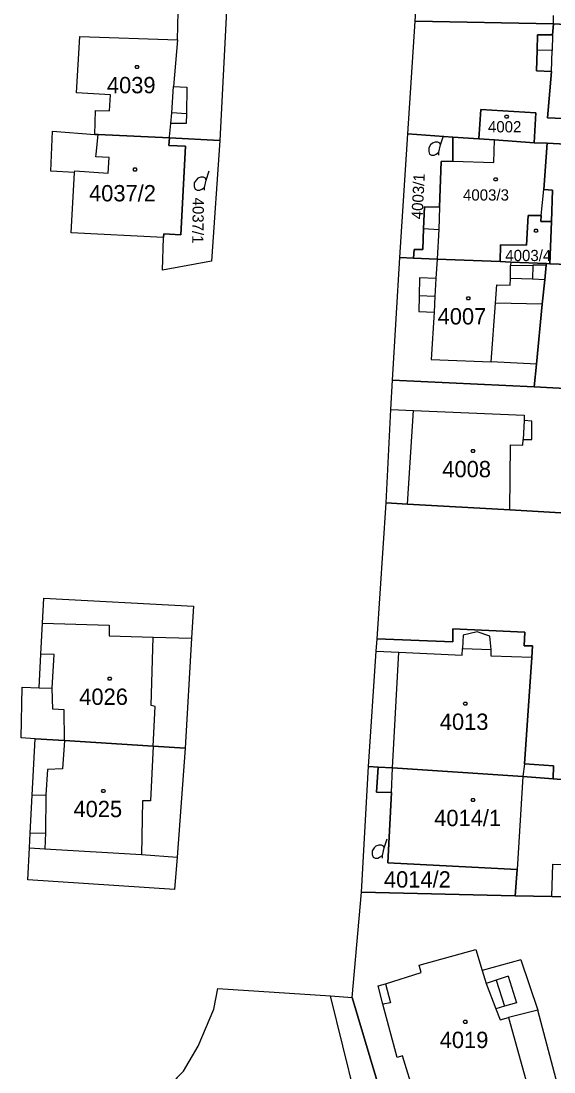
# Model space of a CAD drawing. Extents: x -263587 to -261993, y -1238795 to -1236748.
# Drawn here: x -263052.9 to -263000.7, y -1238246.6 to -1238143.7 of the extents above; entities that cross this region are included whole.
import ezdxf

# ---------------------------------------------------------------- set-up
doc = ezdxf.new("R2010")
doc.units = 0
doc.layers.add('Vrstva 1', color=7, linetype='Continuous')
doc.layers.add('Vrstva 3', color=7, linetype='Continuous')

msp = doc.modelspace()

# ---------------------------------------------------------------- linework, layer by layer
at = {"layer": 'Vrstva 1'}
for p, q in [((-263014.29, -1238143.7), (-263013.36, -1238129.11)), ((-263032.54, -1238138.12), (-263033.41, -1238155.37)), ((-263037.58, -1238145.5), (-263037.41, -1238139.05)), ((-263015.02, -1238154.73), (-263014.29, -1238143.7)), ((-263000.75, -1238143.96), (-263014.29, -1238143.7)), ((-263014.29, -1238143.7), (-263000.75, -1238143.96)), ((-263000.75, -1238143.96), (-263000.77, -1238143.14)), ((-263000.86, -1238145.03), (-263000.75, -1238143.96)), ((-263000.75, -1238143.96), (-263000.86, -1238145.03)), ((-262993.44, -1238144.36), (-263000.75, -1238143.96)), ((-263000.75, -1238143.96), (-262993.44, -1238144.36)), ((-263047.46, -1238150.72), (-263047.14, -1238145.2)), ((-263047.14, -1238145.2), (-263037.58, -1238145.5)), ((-263037.58, -1238145.5), (-263037.96, -1238150.08)), ((-263002.37, -1238146.51), (-263002.34, -1238145.02)), ((-263002.34, -1238145.02), (-263002.37, -1238146.51)), ((-263002.34, -1238145.02), (-263000.86, -1238145.03)), ((-263000.86, -1238145.03), (-263002.34, -1238145.02)), ((-263000.86, -1238145.03), (-263000.91, -1238146.56)), ((-263002.42, -1238148.56), (-263002.37, -1238146.51)), ((-263002.37, -1238146.51), (-263002.42, -1238148.56)), ((-263000.91, -1238146.56), (-263002.37, -1238146.51)), ((-263000.96, -1238148.62), (-263000.91, -1238146.56)), ((-263000.96, -1238148.62), (-263002.42, -1238148.56)), ((-263002.42, -1238148.56), (-263000.96, -1238148.62)), ((-263001.34, -1238153.14), (-263000.96, -1238148.62)), ((-263000.96, -1238148.62), (-263001.34, -1238153.14)), ((-263044.14, -1238150.9), (-263047.46, -1238150.72)), ((-263044.23, -1238152.48), (-263044.14, -1238150.9)), ((-263038.13, -1238152.65), (-263037.96, -1238150.08)), ((-263037.96, -1238150.08), (-263036.65, -1238150.15)), ((-263036.65, -1238150.15), (-263036.7, -1238152.76)), ((-263045.66, -1238154.78), (-263045.6, -1238152.45)), ((-263045.6, -1238152.45), (-263044.23, -1238152.48)), ((-263038.21, -1238153.71), (-263038.13, -1238152.65)), ((-263036.7, -1238152.76), (-263038.13, -1238152.65)), ((-263036.7, -1238152.76), (-263036.72, -1238153.72)), ((-263007.87, -1238152.35), (-263008.06, -1238155.21)), ((-263008.06, -1238155.21), (-263007.87, -1238152.35)), ((-263002.51, -1238152.66), (-263007.87, -1238152.35)), ((-263007.87, -1238152.35), (-263002.51, -1238152.66)), ((-263002.65, -1238155.59), (-263002.51, -1238152.66)), ((-263002.51, -1238152.66), (-263002.65, -1238155.59)), ((-263038.35, -1238155.02), (-263038.21, -1238153.71)), ((-263036.72, -1238153.72), (-263038.21, -1238153.71)), ((-262995.53, -1238153.46), (-263001.34, -1238153.14)), ((-263001.34, -1238153.14), (-262995.53, -1238153.46)), ((-263049.98, -1238158.38), (-263049.8, -1238154.46)), ((-263049.8, -1238154.46), (-263045.66, -1238154.78)), ((-263045.33, -1238154.8), (-263045.66, -1238154.78)), ((-263045.66, -1238154.78), (-263045.33, -1238154.8)), ((-263045.54, -1238156.73), (-263045.33, -1238154.8)), ((-263038.35, -1238155.13), (-263045.33, -1238154.8)), ((-263045.33, -1238154.8), (-263038.35, -1238155.13)), ((-263038.35, -1238155.13), (-263038.41, -1238155.88)), ((-263038.41, -1238155.88), (-263038.35, -1238155.13)), ((-263038.35, -1238155.13), (-263038.35, -1238155.02)), ((-263033.41, -1238155.37), (-263038.35, -1238155.13)), ((-263038.35, -1238155.13), (-263033.41, -1238155.37)), ((-263015.79, -1238166.84), (-263015.02, -1238154.73)), ((-263015.02, -1238154.73), (-263010.63, -1238155.04)), ((-263010.63, -1238155.04), (-263015.02, -1238154.73)), ((-263011.81, -1238155.81), (-263011.54, -1238154.91)), ((-263010.63, -1238155.04), (-263010.61, -1238157.41)), ((-263008.06, -1238155.21), (-263010.63, -1238155.04)), ((-263010.61, -1238157.41), (-263010.63, -1238155.04)), ((-263010.63, -1238155.04), (-263008.06, -1238155.21)), ((-263038.41, -1238155.88), (-263036.77, -1238155.94)), ((-263036.77, -1238155.94), (-263038.41, -1238155.88)), ((-263036.77, -1238155.94), (-263037.25, -1238164.63)), ((-263037.25, -1238164.63), (-263036.77, -1238155.94)), ((-263033.41, -1238155.37), (-263034.23, -1238167.2)), ((-263006.53, -1238155.32), (-263008.06, -1238155.21)), ((-263008.06, -1238155.21), (-263006.53, -1238155.32)), ((-263006.6, -1238157.54), (-263006.53, -1238155.32)), ((-263002.65, -1238155.59), (-263006.53, -1238155.32)), ((-263006.53, -1238155.32), (-263002.65, -1238155.59)), ((-263001.4, -1238155.65), (-263002.65, -1238155.59)), ((-263002.65, -1238155.59), (-263001.4, -1238155.65)), ((-263001.7, -1238160.19), (-263001.4, -1238155.65)), ((-263001.4, -1238155.65), (-263001.7, -1238160.19)), ((-262996.31, -1238155.93), (-263001.4, -1238155.65)), ((-263001.4, -1238155.65), (-262996.31, -1238155.93)), ((-263045.57, -1238156.98), (-263045.54, -1238156.73)), ((-263044.25, -1238157.05), (-263045.57, -1238156.98)), ((-263044.35, -1238158.59), (-263044.25, -1238157.05)), ((-263011.75, -1238157.42), (-263011.92, -1238161.9)), ((-263011.92, -1238161.9), (-263011.75, -1238157.42)), ((-263010.61, -1238157.41), (-263011.75, -1238157.42)), ((-263011.75, -1238157.42), (-263010.61, -1238157.41)), ((-263010.61, -1238157.41), (-263006.6, -1238157.54)), ((-263047.64, -1238158.52), (-263049.98, -1238158.38)), ((-263047.99, -1238164.43), (-263047.64, -1238158.52)), ((-263047.64, -1238158.52), (-263047.63, -1238158.36)), ((-263047.63, -1238158.36), (-263044.35, -1238158.59)), ((-263034.75, -1238159.25), (-263034.48, -1238158.35)), ((-263001.97, -1238162.72), (-263001.7, -1238160.19)), ((-263000.85, -1238160.25), (-263001.7, -1238160.19)), ((-263001.7, -1238160.19), (-263000.85, -1238160.25)), ((-263000.97, -1238163.32), (-263000.85, -1238160.25)), ((-263000.85, -1238160.25), (-263000.97, -1238163.32)), ((-263013.39, -1238161.87), (-263013.48, -1238164.01)), ((-263013.48, -1238164.01), (-263013.39, -1238161.87)), ((-263011.92, -1238161.9), (-263013.39, -1238161.87)), ((-263013.39, -1238161.87), (-263011.92, -1238161.9)), ((-263011.92, -1238161.9), (-263011.99, -1238164.11)), ((-263003.25, -1238162.72), (-263003.41, -1238165.63)), ((-263003.41, -1238165.63), (-263003.25, -1238162.72)), ((-263001.97, -1238162.72), (-263003.25, -1238162.72)), ((-263003.25, -1238162.72), (-263001.97, -1238162.72)), ((-263001.99, -1238163.32), (-263001.97, -1238162.72)), ((-263001.97, -1238162.72), (-263001.99, -1238163.32)), ((-263000.97, -1238163.32), (-263001.99, -1238163.32)), ((-263001.99, -1238163.32), (-263000.97, -1238163.32)), ((-263001.13, -1238167.45), (-263000.97, -1238163.32)), ((-263000.97, -1238163.32), (-263001.13, -1238167.45)), ((-263013.48, -1238164.01), (-263013.54, -1238166.05)), ((-263013.54, -1238166.05), (-263013.48, -1238164.01)), ((-263013.48, -1238164.01), (-263011.99, -1238164.11)), ((-263011.99, -1238164.11), (-263012.15, -1238166.97)), ((-263038.94, -1238164.88), (-263047.99, -1238164.43)), ((-263039.02, -1238168.08), (-263038.94, -1238164.88)), ((-263038.92, -1238164.53), (-263038.94, -1238164.88)), ((-263038.94, -1238164.88), (-263038.92, -1238164.53)), ((-263037.25, -1238164.63), (-263038.92, -1238164.53)), ((-263038.92, -1238164.53), (-263037.25, -1238164.63)), ((-263014.41, -1238166.05), (-263014.47, -1238166.9)), ((-263014.47, -1238166.9), (-263014.41, -1238166.05)), ((-263013.54, -1238166.05), (-263014.41, -1238166.05)), ((-263014.41, -1238166.05), (-263013.54, -1238166.05)), ((-263005.94, -1238165.59), (-263006, -1238167.24)), ((-263006, -1238167.24), (-263005.94, -1238165.59)), ((-263003.41, -1238165.63), (-263005.94, -1238165.59)), ((-263005.94, -1238165.59), (-263003.41, -1238165.63)), ((-263034.23, -1238167.2), (-263039.02, -1238168.08)), ((-263016.52, -1238178.87), (-263015.79, -1238166.84)), ((-263015.79, -1238166.84), (-263014.47, -1238166.9)), ((-263014.47, -1238166.9), (-263015.79, -1238166.84)), ((-263014.47, -1238166.9), (-263012.15, -1238166.99)), ((-263012.15, -1238166.99), (-263014.47, -1238166.9)), ((-263012.15, -1238166.99), (-263012.29, -1238168.89)), ((-263012.15, -1238166.97), (-263012.15, -1238166.99)), ((-263012.15, -1238166.99), (-263006, -1238167.24)), ((-263006, -1238167.24), (-263012.15, -1238166.99)), ((-263006, -1238167.24), (-263004.94, -1238167.29)), ((-263004.94, -1238167.29), (-263006, -1238167.24)), ((-263004.94, -1238167.29), (-263004.96, -1238167.61)), ((-263004.94, -1238167.29), (-263001.46, -1238167.43)), ((-263001.46, -1238167.43), (-263004.94, -1238167.29)), ((-263001.46, -1238167.43), (-263001.48, -1238167.59)), ((-263001.48, -1238167.59), (-263001.46, -1238167.43)), ((-263001.46, -1238167.43), (-263001.13, -1238167.45)), ((-263001.13, -1238167.45), (-263001.46, -1238167.43)), ((-262997.1, -1238167.63), (-263001.13, -1238167.45)), ((-263001.13, -1238167.45), (-262997.1, -1238167.63)), ((-263004.97, -1238168.91), (-263004.96, -1238167.61)), ((-263004.96, -1238167.61), (-263002.8, -1238167.6)), ((-263002.8, -1238167.6), (-263002.83, -1238168.96)), ((-263001.48, -1238167.59), (-263002.8, -1238167.6)), ((-263001.48, -1238167.59), (-263001.62, -1238169.02)), ((-263001.62, -1238169.02), (-263001.48, -1238167.59)), ((-263013.87, -1238168.84), (-263013.92, -1238170.6)), ((-263012.29, -1238168.89), (-263013.87, -1238168.84)), ((-263012.29, -1238168.89), (-263012.39, -1238170.66)), ((-263006.43, -1238171.3), (-263006.31, -1238169.53)), ((-263006.31, -1238169.53), (-263005, -1238169.54)), ((-263005, -1238169.54), (-263004.97, -1238168.91)), ((-263002.83, -1238168.96), (-263004.97, -1238168.91)), ((-263001.62, -1238169.02), (-263002.83, -1238168.96)), ((-263001.62, -1238169.02), (-263001.86, -1238171.42)), ((-263001.86, -1238171.42), (-263001.62, -1238169.02)), ((-263013.92, -1238170.6), (-263013.96, -1238172.12)), ((-263012.39, -1238170.66), (-263013.92, -1238170.6)), ((-263012.39, -1238170.66), (-263012.45, -1238172.19)), ((-263006.86, -1238177.07), (-263006.43, -1238171.3)), ((-263001.86, -1238171.42), (-263006.43, -1238171.3)), ((-263001.86, -1238171.42), (-263002.44, -1238177.29)), ((-263002.44, -1238177.29), (-263001.86, -1238171.42)), ((-263013.96, -1238172.12), (-263012.45, -1238172.19)), ((-263012.45, -1238172.19), (-263012.75, -1238176.84)), ((-263012.75, -1238176.84), (-263006.86, -1238177.07)), ((-263002.44, -1238177.29), (-263006.86, -1238177.07)), ((-263002.44, -1238177.29), (-263002.66, -1238179.51)), ((-263002.66, -1238179.51), (-263002.44, -1238177.29)), ((-263016.67, -1238181.72), (-263016.52, -1238178.87)), ((-263016.52, -1238178.87), (-263002.66, -1238179.51)), ((-263002.66, -1238179.51), (-263016.52, -1238178.87)), ((-263002.66, -1238179.51), (-262987.5, -1238180.36)), ((-262987.5, -1238180.36), (-263002.66, -1238179.51)), ((-263017.14, -1238190.88), (-263016.67, -1238181.72)), ((-263016.67, -1238181.72), (-263014.46, -1238181.83)), ((-263015.07, -1238190.99), (-263014.46, -1238181.83)), ((-263014.46, -1238181.83), (-263003.62, -1238182.27)), ((-263003.65, -1238182.82), (-263003.73, -1238184.68)), ((-263003.62, -1238182.27), (-263003.65, -1238182.82)), ((-263002.89, -1238182.87), (-263003.65, -1238182.82)), ((-263002.89, -1238184.68), (-263002.89, -1238182.87)), ((-263003.76, -1238185.21), (-263003.73, -1238184.68)), ((-263003.73, -1238184.68), (-263002.89, -1238184.68)), ((-263005.05, -1238191.56), (-263004.96, -1238185.19)), ((-263004.96, -1238185.19), (-263003.76, -1238185.21)), ((-263018.03, -1238204.21), (-263017.14, -1238190.88)), ((-263015.07, -1238190.99), (-263017.14, -1238190.88)), ((-263017.14, -1238190.88), (-263015.07, -1238190.99)), ((-263005.05, -1238191.56), (-263015.07, -1238190.99)), ((-263015.07, -1238190.99), (-263005.05, -1238191.56)), ((-262998.22, -1238191.96), (-263005.05, -1238191.56)), ((-263005.05, -1238191.56), (-262998.22, -1238191.96)), ((-263050.78, -1238202.68), (-263050.65, -1238200.22)), ((-263050.65, -1238200.22), (-263036.01, -1238201.01)), ((-263036.01, -1238201.01), (-263036.19, -1238204.09)), ((-263050.94, -1238205.69), (-263050.78, -1238202.68)), ((-263050.78, -1238202.68), (-263044.25, -1238202.86)), ((-263044.25, -1238202.86), (-263044.24, -1238203.89)), ((-263003.57, -1238203.53), (-263010.62, -1238203.23)), ((-263010.62, -1238203.23), (-263010.62, -1238204.48)), ((-263010.62, -1238204.48), (-263010.62, -1238203.23)), ((-263010.62, -1238203.23), (-263003.57, -1238203.53)), ((-263008.23, -1238203.5), (-263009.62, -1238203.84)), ((-263007.01, -1238203.94), (-263008.23, -1238203.5)), ((-263003.62, -1238204.87), (-263003.57, -1238203.53)), ((-263003.57, -1238203.53), (-263003.62, -1238204.87)), ((-263044.24, -1238203.89), (-263039.94, -1238204.05)), ((-263040.13, -1238210.73), (-263039.94, -1238204.05)), ((-263039.94, -1238204.05), (-263036.19, -1238204.12)), ((-263036.19, -1238204.12), (-263036.8, -1238214.92)), ((-263036.19, -1238204.09), (-263036.19, -1238204.12)), ((-263018.11, -1238205.42), (-263018.03, -1238204.21)), ((-263010.62, -1238204.48), (-263018.03, -1238204.21)), ((-263018.03, -1238204.21), (-263010.62, -1238204.48)), ((-263009.62, -1238203.84), (-263009.68, -1238205.15)), ((-263006.88, -1238205.25), (-263007.01, -1238203.94)), ((-263018.86, -1238216.7), (-263018.11, -1238205.42)), ((-263018.11, -1238205.42), (-263015.89, -1238205.49)), ((-263016.51, -1238216.85), (-263015.89, -1238205.49)), ((-263015.89, -1238205.49), (-263009.7, -1238205.8)), ((-263009.7, -1238205.8), (-263009.68, -1238205.15)), ((-263009.68, -1238205.15), (-263006.88, -1238205.25)), ((-263006.86, -1238205.91), (-263006.88, -1238205.25)), ((-263002.81, -1238204.89), (-263003.62, -1238204.87)), ((-263003.62, -1238204.87), (-263002.81, -1238204.89)), ((-263002.89, -1238206.03), (-263002.81, -1238204.89)), ((-263002.81, -1238204.89), (-263002.89, -1238206.03)), ((-263051.11, -1238209), (-263050.94, -1238205.69)), ((-263049.64, -1238205.72), (-263050.94, -1238205.69)), ((-263049.82, -1238209.02), (-263049.64, -1238205.72)), ((-263002.89, -1238206.03), (-263006.86, -1238205.91)), ((-263003.59, -1238216.46), (-263002.89, -1238206.03)), ((-263002.89, -1238206.03), (-263003.59, -1238216.46)), ((-263052.88, -1238213.91), (-263052.76, -1238208.92)), ((-263052.76, -1238208.92), (-263051.11, -1238209)), ((-263051.11, -1238209), (-263049.82, -1238209.02)), ((-263049.76, -1238211.09), (-263049.82, -1238209.02)), ((-263039.74, -1238210.82), (-263040.13, -1238210.73)), ((-263048.67, -1238211.14), (-263049.76, -1238211.09)), ((-263048.64, -1238214.17), (-263048.67, -1238211.14)), ((-263039.96, -1238214.72), (-263039.74, -1238210.82)), ((-263051.49, -1238213.99), (-263052.88, -1238213.91)), ((-263051.79, -1238219.53), (-263051.49, -1238213.99)), ((-263051.49, -1238213.99), (-263048.64, -1238214.17)), ((-263048.64, -1238214.17), (-263051.49, -1238213.99)), ((-263048.64, -1238214.17), (-263048.83, -1238216.95)), ((-263048.64, -1238214.17), (-263039.96, -1238214.72)), ((-263039.96, -1238214.72), (-263048.64, -1238214.17)), ((-263039.96, -1238214.72), (-263040.21, -1238220.08)), ((-263039.96, -1238214.72), (-263036.8, -1238214.92)), ((-263036.8, -1238214.92), (-263039.96, -1238214.72)), ((-263036.8, -1238214.92), (-263037.61, -1238225.58)), ((-263019.56, -1238229.02), (-263018.86, -1238216.7)), ((-263017.93, -1238216.76), (-263018.86, -1238216.7)), ((-263018.86, -1238216.7), (-263017.93, -1238216.76)), ((-263018.09, -1238219.22), (-263017.93, -1238216.76)), ((-263017.93, -1238216.76), (-263018.09, -1238219.22)), ((-263016.51, -1238216.85), (-263017.93, -1238216.76)), ((-263017.93, -1238216.76), (-263016.51, -1238216.85)), ((-263016.62, -1238219.25), (-263016.51, -1238216.85)), ((-263003.77, -1238217.68), (-263016.51, -1238216.85)), ((-263016.51, -1238216.85), (-263003.77, -1238217.68)), ((-263003.59, -1238216.46), (-263003.77, -1238217.68)), ((-263000.75, -1238216.64), (-263003.59, -1238216.46)), ((-263003.59, -1238216.46), (-263000.75, -1238216.64)), ((-263000.79, -1238217.93), (-263000.75, -1238216.64)), ((-263000.75, -1238216.64), (-263000.79, -1238217.93)), ((-263050.3, -1238216.99), (-263050.44, -1238219.49)), ((-263048.83, -1238216.95), (-263050.3, -1238216.99)), ((-263003.77, -1238217.68), (-263004.32, -1238226.79)), ((-263000.79, -1238217.93), (-263003.77, -1238217.68)), ((-263003.77, -1238217.68), (-263000.79, -1238217.93)), ((-262993.35, -1238218.47), (-263000.79, -1238217.93)), ((-263000.79, -1238217.93), (-262993.35, -1238218.47)), ((-263051.98, -1238223.24), (-263051.79, -1238219.53)), ((-263051.79, -1238219.53), (-263050.44, -1238219.49)), ((-263050.44, -1238219.49), (-263050.47, -1238223.19)), ((-263016.62, -1238219.25), (-263018.09, -1238219.22)), ((-263018.09, -1238219.22), (-263016.62, -1238219.25)), ((-263016.99, -1238226.15), (-263016.62, -1238219.25)), ((-263016.62, -1238219.25), (-263016.99, -1238226.15)), ((-263040.98, -1238220.08), (-263041.1, -1238225.34)), ((-263040.21, -1238220.08), (-263040.98, -1238220.08)), ((-263052.06, -1238224.67), (-263051.98, -1238223.24)), ((-263051.98, -1238223.24), (-263050.47, -1238223.19)), ((-263050.47, -1238223.19), (-263050.54, -1238224.76)), ((-263017.33, -1238224.69), (-263017.06, -1238223.79)), ((-263052.22, -1238227.8), (-263052.06, -1238224.67)), ((-263052.06, -1238224.67), (-263050.54, -1238224.76)), ((-263050.54, -1238224.76), (-263041.1, -1238225.34)), ((-263041.1, -1238225.34), (-263037.61, -1238225.58)), ((-263037.61, -1238225.58), (-263037.85, -1238228.75)), ((-263004.32, -1238226.79), (-263016.99, -1238226.15)), ((-263016.99, -1238226.15), (-263004.32, -1238226.79)), ((-263004.52, -1238229.37), (-263004.32, -1238226.79)), ((-263004.32, -1238226.79), (-263004.52, -1238229.37)), ((-263000.94, -1238229.45), (-263000.82, -1238226.26)), ((-263000.82, -1238226.26), (-262995.25, -1238226.36)), ((-263037.85, -1238228.75), (-263052.22, -1238227.8)), ((-263020.46, -1238239.35), (-263019.56, -1238229.02)), ((-263019.56, -1238229.02), (-263004.52, -1238229.37)), ((-263004.52, -1238229.37), (-263019.56, -1238229.02)), ((-263004.52, -1238229.37), (-263000.94, -1238229.45)), ((-263000.94, -1238229.45), (-263004.52, -1238229.37)), ((-263000.94, -1238229.45), (-262995.12, -1238229.58)), ((-262995.12, -1238229.58), (-263000.94, -1238229.45)), ((-263013.9, -1238236.16), (-263008.37, -1238234.63)), ((-263008.37, -1238234.63), (-263007.74, -1238236.69)), ((-263013.71, -1238236.89), (-263013.9, -1238236.16)), ((-263003.95, -1238235.65), (-263007.74, -1238236.69)), ((-263003.95, -1238235.65), (-263002.31, -1238240.58)), ((-263017.22, -1238238), (-263013.71, -1238236.89)), ((-263007.74, -1238236.69), (-263007.37, -1238237.96)), ((-263005.2, -1238237.24), (-263006.38, -1238237.63)), ((-263005.2, -1238237.24), (-263004.38, -1238239.86)), ((-263034.01, -1238240.49), (-263033.61, -1238238.45)), ((-263033.61, -1238238.45), (-263022.59, -1238239.19)), ((-263017.91, -1238238.19), (-263017.22, -1238238)), ((-263017.48, -1238239.99), (-263017.91, -1238238.19)), ((-263017.22, -1238238), (-263016.73, -1238239.87)), ((-263006.38, -1238237.63), (-263007.37, -1238237.96)), ((-263007.37, -1238237.96), (-263006.41, -1238240.45)), ((-263006.38, -1238237.63), (-263005.56, -1238240.18)), ((-263022.59, -1238239.19), (-263020.46, -1238239.35)), ((-263018.78, -1238254.62), (-263022.59, -1238239.19)), ((-263015.99, -1238254.37), (-263020.46, -1238239.35)), ((-263020.46, -1238239.35), (-263015.99, -1238254.37)), ((-263035.53, -1238244.09), (-263034.01, -1238240.49)), ((-263016.73, -1238239.87), (-263017.48, -1238239.99)), ((-263016.08, -1238245.22), (-263017.48, -1238239.99)), ((-263005.56, -1238240.18), (-263006.41, -1238240.45)), ((-263006.41, -1238240.45), (-263006, -1238241.52)), ((-263004.38, -1238239.86), (-263005.56, -1238240.18)), ((-263002.31, -1238240.58), (-263005.18, -1238241.31)), ((-262999.91, -1238249.59), (-263002.31, -1238240.58)), ((-263006, -1238241.52), (-263005.18, -1238241.31)), ((-263005.18, -1238241.31), (-263003.46, -1238247.42)), ((-263036.98, -1238246.57), (-263035.53, -1238244.09)), ((-263015.54, -1238245.06), (-263016.08, -1238245.22)), ((-263013.91, -1238250.27), (-263015.54, -1238245.06)), ((-263047.01, -1238256.8), (-263036.98, -1238246.57))]:
    msp.add_line(p, q, dxfattribs=at)
for points in [[(-263041.44, -1238148.03), (-263041.35, -1238148.18), (-263041.44, -1238148.33), (-263041.62, -1238148.33), (-263041.71, -1238148.18), (-263041.62, -1238148.03)], [(-263005.27, -1238152.88), (-263005.18, -1238153.03), (-263005.27, -1238153.18), (-263005.45, -1238153.18), (-263005.54, -1238153.03), (-263005.45, -1238152.88)], [(-263041.63, -1238158.07), (-263041.54, -1238158.22), (-263041.63, -1238158.37), (-263041.81, -1238158.37), (-263041.9, -1238158.22), (-263041.81, -1238158.07)], [(-263006.35, -1238159.04), (-263006.26, -1238159.19), (-263006.35, -1238159.34), (-263006.53, -1238159.34), (-263006.62, -1238159.19), (-263006.53, -1238159.04)], [(-263002.38, -1238164.07), (-263002.29, -1238164.22), (-263002.38, -1238164.37), (-263002.56, -1238164.37), (-263002.65, -1238164.22), (-263002.56, -1238164.07)], [(-263009.01, -1238170.68), (-263008.92, -1238170.83), (-263009.01, -1238170.98), (-263009.19, -1238170.98), (-263009.28, -1238170.83), (-263009.19, -1238170.68)], [(-263008.55, -1238185.65), (-263008.46, -1238185.8), (-263008.55, -1238185.95), (-263008.73, -1238185.95), (-263008.82, -1238185.8), (-263008.73, -1238185.65)], [(-263044.11, -1238207.95), (-263044.02, -1238208.1), (-263044.11, -1238208.25), (-263044.29, -1238208.25), (-263044.38, -1238208.1), (-263044.29, -1238207.95)], [(-263009.32, -1238210.4), (-263009.23, -1238210.55), (-263009.32, -1238210.7), (-263009.5, -1238210.7), (-263009.59, -1238210.55), (-263009.5, -1238210.4)], [(-263044.72, -1238218.95), (-263044.63, -1238219.1), (-263044.72, -1238219.25), (-263044.9, -1238219.25), (-263044.99, -1238219.1), (-263044.9, -1238218.95)], [(-263008.55, -1238219.83), (-263008.46, -1238219.98), (-263008.55, -1238220.13), (-263008.73, -1238220.13), (-263008.82, -1238219.98), (-263008.73, -1238219.83)], [(-263009.32, -1238241.57), (-263009.23, -1238241.72), (-263009.32, -1238241.87), (-263009.5, -1238241.87), (-263009.59, -1238241.72), (-263009.5, -1238241.57)]]:
    msp.add_lwpolyline(points, close=True, dxfattribs=at)
for points in [[(-263011.99, -1238156.8), (-263011.99, -1238156.53), (-263011.81, -1238155.81), (-263011.9, -1238155.63), (-263012.08, -1238155.54), (-263012.35, -1238155.54), (-263012.62, -1238155.63), (-263012.8, -1238155.81), (-263012.98, -1238156.08), (-263012.98, -1238156.44), (-263012.89, -1238156.71), (-263012.71, -1238156.8), (-263012.44, -1238156.8), (-263012.26, -1238156.71), (-263011.99, -1238156.53)], [(-263034.93, -1238160.24), (-263034.93, -1238159.97), (-263034.75, -1238159.25), (-263034.84, -1238159.07), (-263035.02, -1238158.98), (-263035.29, -1238158.98), (-263035.56, -1238159.07), (-263035.74, -1238159.25), (-263035.92, -1238159.52), (-263035.92, -1238159.88), (-263035.83, -1238160.15), (-263035.65, -1238160.24), (-263035.38, -1238160.24), (-263035.2, -1238160.15), (-263034.93, -1238159.97)], [(-263017.51, -1238225.68), (-263017.51, -1238225.41), (-263017.33, -1238224.69), (-263017.42, -1238224.51), (-263017.6, -1238224.42), (-263017.87, -1238224.42), (-263018.14, -1238224.51), (-263018.32, -1238224.69), (-263018.5, -1238224.96), (-263018.5, -1238225.32), (-263018.41, -1238225.59), (-263018.23, -1238225.68), (-263017.96, -1238225.68), (-263017.78, -1238225.59), (-263017.51, -1238225.41)]]:
    msp.add_lwpolyline(points, dxfattribs=at)
at = {"layer": 'Vrstva 3'}
msp.add_lwpolyline([(-263045.31, -1238265.66), (-263045.89, -1238264.91), (-263049.15, -1238263.32), (-263052.633, -1238262.289), (-263047.01, -1238256.8), (-263036.98, -1238246.57), (-263035.53, -1238244.09), (-263034.01, -1238240.49), (-263033.61, -1238238.45), (-263022.59, -1238239.19), (-263020.46, -1238239.35), (-263015.99, -1238254.37)], close=True, dxfattribs=at)

# ---------------------------------------------------------------- texts
at = {"layer": 'Vrstva 1'}
for s, height, p in [('4039', 1.6, (-263044.473, -1238150.75)), ('4002', 1.1, (-263007.178, -1238154.58)), ('4037/2', 1.6, (-263046.222, -1238161.34)), ('4003/3', 1.1, (-263009.623, -1238161.26)), ('4003/4', 1.1, (-263005.483, -1238167.19)), ('4007', 1.6, (-263012.106, -1238173.4)), ('4008', 1.6, (-263011.646, -1238188.37)), ('4026', 1.6, (-263047.181, -1238210.67)), ('4013', 1.6, (-263011.893, -1238213.12)), ('4025', 1.6, (-263047.747, -1238221.67)), ('4014/1', 1.6, (-263012.44, -1238222.55)), ('4014/2', 1.6, (-263017.359, -1238228.57)), ('4019', 1.6, (-263011.9, -1238244.29))]:
    msp.add_text(s, height=height, dxfattribs=at).set_placement(p)
for s, rotation, p in [('4003/1', 87.08959, (-263013.583, -1238163.115)), ('4037/1', 269.23287, (-263036.073, -1238160.96))]:
    msp.add_text(s, height=1.1, rotation=rotation, dxfattribs=at).set_placement(p)

doc.saveas('drawing.dxf')
